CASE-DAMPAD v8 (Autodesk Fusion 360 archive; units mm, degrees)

design "CASE-DAMPAD" references "DAMPAD"
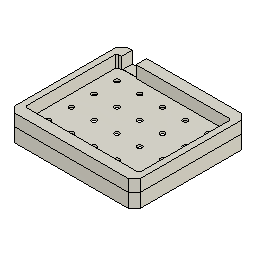
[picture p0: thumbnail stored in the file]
component_insert "コンポーネントの挿入"
ground "固定"
sketch "スケッチ1" plane through (0, 0, 0) normal (0, 0, -1) x axis (1, 0, 0)
  line L1 (2, -78.6) -> (0, -76.6)
  line L2 (95.1, -78.6) -> (2, -78.6)
  line L3 (97.1, -76.6) -> (95.1, -78.6)
  line L4 (97.1, -2) -> (97.1, -76.6)
  line L5 (95.1, 0) -> (97.1, -2)
  line L6 (2, 0) -> (95.1, 0)
  line L7 (0, -2) -> (2, 0)
  line L8 (0, -76.6) -> (0, -2)
  line L9 (-0.2, -76.6828) -> (-0.2, -1.9172)
  line L10 (1.9172, -78.8) -> (-0.2, -76.6828)
  line L11 (95.1828, -78.8) -> (1.9172, -78.8)
  line L12 (97.3, -76.6828) -> (95.1828, -78.8)
  line L13 (97.3, -1.9172) -> (97.3, -76.6828)
  line L14 (95.1828, 0.2) -> (97.3, -1.9172)
  line L15 (1.9172, 0.2) -> (95.1828, 0.2)
  line L16 (-0.2, -1.9172) -> (1.9172, 0.2)
  line L17 (-4, 2.7681) -> (1.2319, 8)
  line L18 (-4, -81.3681) -> (-4, 2.7681)
  line L19 (1.2319, -86.6) -> (-4, -81.3681)
  line L20 (95.8681, -86.6) -> (1.2319, -86.6)
  line L21 (101.1, -81.3681) -> (95.8681, -86.6)
  line L22 (101.1, 2.7681) -> (101.1, -81.3681)
  line L23 (95.8681, 8) -> (101.1, 2.7681)
  line L24 (1.2319, 8) -> (95.8681, 8)
  line L25 (1, -76.1858) -> (1, -2.4142)
  line L26 (2.4142, -77.6) -> (1, -76.1858)
  line L27 (94.6858, -77.6) -> (2.4142, -77.6)
  line L28 (96.1, -76.1858) -> (94.6858, -77.6)
  line L29 (96.1, -2.4142) -> (96.1, -76.1858)
  line L30 (94.6858, -1) -> (96.1, -2.4142)
  line L31 (2.4142, -1) -> (94.6858, -1)
  line L32 (1, -2.4142) -> (2.4142, -1)
  circle C1 centre (67.75, -68) radius 2
  circle C2 centre (10.6, -10.85) radius 2
  circle C3 centre (86.8, -29.9) radius 2
  circle C4 centre (67.75, -48.95) radius 2
  circle C5 centre (67.75, -10.85) radius 2
  circle C6 centre (10.6, -48.95) radius 2
  circle C7 centre (86.8, -48.95) radius 2
  circle C8 centre (48.7, -29.9) radius 2
  circle C9 centre (29.65, -10.85) radius 2
  circle C10 centre (48.7, -68) radius 2
  circle C11 centre (10.6, -68) radius 2
  circle C12 centre (48.7, -10.85) radius 2
  circle C13 centre (29.65, -48.95) radius 2
  circle C14 centre (67.75, -29.9) radius 2
  circle C15 centre (86.8, -10.85) radius 2
  circle C16 centre (10.6, -29.9) radius 2
  circle C17 centre (48.7, -48.95) radius 2
  circle C18 centre (29.65, -29.9) radius 2
  circle C19 centre (29.65, -68) radius 2
  circle C20 centre (86.8, -68) radius 2
  parallel L7 L17
  parallel L8 L18
  parallel L1 L19
  parallel L2 L20
  parallel L3 L21
  parallel L4 L22
  parallel L5 L23
  parallel L6 L24
  dimension "d1" = 0.2
  dimension "d3" = -1
  dimension "d23" distance L4 L22 = 4
  dimension "d24" distance L8 L18 = 4
  dimension "d25" distance L2 L20 = 8
  dimension "d26" distance L6 L24 = 8
  dimension "d27" distance L16 L17 = 6 (= "d30")
  dimension "d28" distance L14 L23 = 6 (= "d30")
  dimension "d29" distance L12 L21 = 6 (= "d30")
  dimension "d30" distance L10 L19 = 6
extrude "押し出し1" new body sketch "スケッチ1" profile of L1 L2 L3 L4 L5 L6 L7 L8 L13 L9 L16 L10 L11 L12 L15 L14 L19 L17 L22 L18 L20 L21 L24 L23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 along normal blind 10 bodies "Bottom"
extrude "押し出し2" add sketch "スケッチ1" profile of L13 L9 L16 L10 L11 L12 L15 L14 L19 L17 L22 L18 L20 L21 L24 L23 against normal blind 1.6
sketch "スケッチ2" plane through (0, 0, 1.6) normal (0, 0, 1) x axis (-1, 0, 0)
  line L1 (0, -76.6) -> (-2, -78.6)
  line L2 (0, -2) -> (0, -76.6)
  line L3 (-2, 0) -> (0, -2)
  line L4 (-95.1, 0) -> (-2, 0)
  line L5 (-97.1, -2) -> (-95.1, 0)
  line L6 (-97.1, -76.6) -> (-97.1, -2)
  line L7 (-95.1, -78.6) -> (-97.1, -76.6)
  line L8 (-2, -78.6) -> (-95.1, -78.6)
  line L9 (-0.8, -2.3314) -> (-0.8, -76.2686)
  line L10 (-2.3314, -0.8) -> (-0.8, -2.3314)
  line L11 (-94.7686, -0.8) -> (-2.3314, -0.8)
  line L12 (-96.3, -2.3314) -> (-94.7686, -0.8)
  line L13 (-96.3, -76.2686) -> (-96.3, -2.3314)
  line L14 (-94.7686, -77.8) -> (-96.3, -76.2686)
  line L15 (-2.3314, -77.8) -> (-94.7686, -77.8)
  line L16 (-0.8, -76.2686) -> (-2.3314, -77.8)
  line L17 (-1.8, -75.3568) -> (-1.8, -74.5354)
  line L18 (-1.8, -89.3214) -> (-1.8, -75.3568)
  line L19 (-10.8, -68.2718) -> (-10.8, -89.3214)
  line L20 (-4.8, -77.8) -> (-4.8, -86.6)
  line L21 (-16.8, -77.8) -> (-16.8, -86.6)
  line L22 (0.2, -1.9172) -> (-1.9172, 0.2)
  line L23 (0.2, -76.6828) -> (0.2, -1.9172)
  line L24 (-1.9172, -78.8) -> (0.2, -76.6828)
  line L25 (-95.1828, -78.8) -> (-1.9172, -78.8)
  line L26 (-97.3, -76.6828) -> (-95.1828, -78.8)
  line L27 (-97.3, -1.9172) -> (-97.3, -76.6828)
  line L28 (-95.1828, 0.2) -> (-97.3, -1.9172)
  line L29 (-1.9172, 0.2) -> (-95.1828, 0.2)
  line L30 (-95.8681, 8) -> (-1.2319, 8)
  line L31 (-101.1, 2.7681) -> (-95.8681, 8)
  line L32 (-101.1, -81.3681) -> (-101.1, 2.7681)
  line L33 (-95.8681, -86.6) -> (-101.1, -81.3681)
  line L34 (-1.2319, -86.6) -> (-95.8681, -86.6)
  line L35 (4, -81.3681) -> (-1.2319, -86.6)
  line L36 (4, 2.7681) -> (4, -81.3681)
  line L37 (-1.2319, 8) -> (4, 2.7681)
  circle C1 centre (-67.75, -68) radius 2
  circle C2 centre (-10.6, -10.85) radius 2
  circle C3 centre (-86.8, -29.9) radius 2
  circle C4 centre (-67.75, -48.95) radius 2
  circle C5 centre (-67.75, -10.85) radius 2
  circle C6 centre (-10.6, -48.95) radius 2
  circle C7 centre (-86.8, -48.95) radius 2
  circle C8 centre (-48.7, -29.9) radius 2
  circle C9 centre (-29.65, -10.85) radius 2
  circle C10 centre (-48.7, -68) radius 2
  circle C11 centre (-10.6, -68) radius 2
  circle C12 centre (-48.7, -10.85) radius 2
  circle C13 centre (-29.65, -48.95) radius 2
  circle C14 centre (-67.75, -29.9) radius 2
  circle C15 centre (-86.8, -10.85) radius 2
  circle C16 centre (-10.6, -29.9) radius 2
  circle C17 centre (-48.7, -48.95) radius 2
  circle C18 centre (-29.65, -29.9) radius 2
  circle C19 centre (-29.65, -68) radius 2
  circle C20 centre (-86.8, -68) radius 2
  point P23 (-4.8, -77.8)
  point P24 (-16.8, -77.8)
  point P41 (-16.8, -86.6)
  point P42 (-4.8, -86.6)
  vertical L17
  parallel L17 L18
  perpendicular L15 L19
  coincident L15 P23
  perpendicular L15 L20
  coincident L15 P24
  perpendicular L15 L21
  symmetric L19 L20 L21
  coincident L34 P41
  coincident L34 P42
  dimension "d9" = -0.8
  dimension "d13" distance L9 L18 = 1
  dimension "d14" distance L18 L19 = 9
  dimension "d15" distance L20 L21 = 12
extrude "押し出し5" new body sketch "スケッチ2" profile of L1 L2 L3 L4 L5 L6 L7 L8 L9 L10 L12 L11 L16 L13 L14 L15 L20 L21 L22 L23 L24 L25 L26 L27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 along normal blind 10 bodies "Top"
sketch "スケッチ3" plane through (0, 0, 11.6) normal (0, 0, 1) x axis (-1, 0, 0)
  line L1 (-93.1, 4) -> (-4, 4)
  line L2 (-3, 4) -> (-3.5, 3.134)
  line L3 (-3.5, 4.866) -> (-3, 4)
  line L4 (-4.5, 4.866) -> (-3.5, 4.866)
  line L5 (-5, 4) -> (-4.5, 4.866)
  line L6 (-4.5, 3.134) -> (-5, 4)
  line L7 (-3.5, 3.134) -> (-4.5, 3.134)
  line L8 (-2.4142, -77.6) -> (-1, -76.1858)
  line L9 (-94.6858, -77.6) -> (-17, -77.6)
  line L10 (-96.1, -76.1858) -> (-94.6858, -77.6)
  line L11 (-96.1, -2.4142) -> (-96.1, -76.1858)
  line L12 (-94.6858, -1) -> (-96.1, -2.4142)
  line L13 (-2.4142, -1) -> (-94.6858, -1)
  line L14 (-1, -2.4142) -> (-2.4142, -1)
  line L15 (-1, -76.1858) -> (-1, -2.4142)
  line L16 (-95.8681, 8) -> (-1.2319, 8)
  line L17 (-101.1, -81.3681) -> (-101.1, 2.7681)
  line L18 (-93.6, 4.866) -> (-92.6, 4.866)
  line L19 (-94.1, 4) -> (-93.6, 4.866)
  line L20 (-92.6, 4.866) -> (-92.1, 4)
  line L21 (-92.1, 4) -> (-92.6, 3.134)
  line L22 (-93.6, 3.134) -> (-94.1, 4)
  line L23 (-92.6, 3.134) -> (-93.6, 3.134)
  line L24 (-17, -77.6) -> (-17, -86.6)
  line L25 (-5, -77.6) -> (-2.4142, -77.6)
  line L26 (-5, -86.6) -> (-5, -77.6)
  line L27 (-3.5, -82.6) -> (-3, -81.734)
  line L28 (-2, -81.734) -> (-1.5, -82.6)
  line L29 (-1.5, -82.6) -> (-2, -83.466)
  line L30 (-3, -81.734) -> (-2, -81.734)
  line L31 (-2, -83.466) -> (-3, -83.466)
  line L32 (-3, -83.466) -> (-3.5, -82.6)
  line L33 (-17, -86.6) -> (-95.8681, -86.6)
  line L34 (-93.1, -82.6) -> (-2.5, -82.6)
  line L35 (-20.5, -82.6) -> (-20, -81.734)
  line L36 (-19, -83.466) -> (-20, -83.466)
  line L37 (-19, -81.734) -> (-18.5, -82.6)
  line L38 (-20, -83.466) -> (-20.5, -82.6)
  line L39 (-20, -81.734) -> (-19, -81.734)
  line L40 (-18.5, -82.6) -> (-19, -83.466)
  line L41 (-94.1, -82.6) -> (-93.6, -81.734)
  line L42 (-92.6, -83.466) -> (-93.6, -83.466)
  line L43 (-92.6, -81.734) -> (-92.1, -82.6)
  line L44 (-93.6, -83.466) -> (-94.1, -82.6)
  line L45 (-93.6, -81.734) -> (-92.6, -81.734)
  line L46 (-92.1, -82.6) -> (-92.6, -83.466)
  line L47 (-17, -77.6) -> (-17, -86.6)
  line L48 (-5, -86.6) -> (-5, -77.6)
  line L49 (4, 2.7681) -> (4, -81.3681)
  line L50 (-1.2319, -86.6) -> (-5, -86.6)
  line L51 (4, -81.3681) -> (-1.2319, -86.6)
  line L52 (4, 2.7681) -> (4, -81.3681)
  line L53 (-1.2319, 8) -> (4, 2.7681)
  line L54 (-95.8681, 8) -> (-1.2319, 8)
  line L55 (-101.1, 2.7681) -> (-95.8681, 8)
  line L56 (-101.1, -81.3681) -> (-101.1, 2.7681)
  line L57 (-95.8681, -86.6) -> (-101.1, -81.3681)
  line L58 (-17, -86.6) -> (-95.8681, -86.6)
  line L59 (-1.2319, -86.6) -> (-4.8, -86.6)
  line L60 (4, -81.3681) -> (-1.2319, -86.6)
  line L61 (4, 2.7681) -> (4, -81.3681)
  line L62 (-1.2319, 8) -> (4, 2.7681)
  line L63 (-95.8681, 8) -> (-1.2319, 8)
  line L64 (-101.1, 2.7681) -> (-95.8681, 8)
  line L65 (-101.1, -81.3681) -> (-101.1, 2.7681)
  line L66 (-95.8681, -86.6) -> (-101.1, -81.3681)
  line L67 (-16.8, -86.6) -> (-95.8681, -86.6)
  line L68 (-16.8, -77.8) -> (-16.8, -86.6)
  line L69 (-94.7686, -77.8) -> (-16.8, -77.8)
  line L70 (-96.3, -76.2686) -> (-94.7686, -77.8)
  line L71 (-96.3, -2.3314) -> (-96.3, -76.2686)
  line L72 (-94.7686, -0.8) -> (-96.3, -2.3314)
  line L73 (-2.3314, -0.8) -> (-94.7686, -0.8)
  line L74 (-0.8, -2.3314) -> (-2.3314, -0.8)
  line L75 (-0.8, -76.2686) -> (-0.8, -2.3314)
  line L76 (-2.3314, -77.8) -> (-0.8, -76.2686)
  line L77 (-4.8, -77.8) -> (-2.3314, -77.8)
  line L78 (-4.8, -86.6) -> (-4.8, -77.8)
  circle C1 centre (-4, 4) radius 1.2
  circle C2 centre (-4, 4) radius 1.95
  circle C3 centre (-4, 4) radius 1
  circle C4 centre (-93.1, 4) radius 1.95
  circle C5 centre (-93.1, 4) radius 1
  circle C6 centre (-93.1, 4) radius 1.2
  circle C7 centre (-2.5, -82.6) radius 1.95
  circle C8 centre (-2.5, -82.6) radius 1.2
  circle C9 centre (-2.5, -82.6) radius 1
  circle C10 centre (-19.5, -82.6) radius 1.2
  circle C11 centre (-19.5, -82.6) radius 1.95
  circle C12 centre (-19.5, -82.6) radius 1
  circle C13 centre (-93.1, -82.6) radius 1.2
  circle C14 centre (-93.1, -82.6) radius 1.95
  circle C15 centre (-93.1, -82.6) radius 1
  point P2 (-4, 4)
  point P3 (-4, 4)
  point P5 (-4, 4)
  point P13 (-4, 4)
  point P12 (-4.5, 3.134)
  point P30 (-93.1, 4)
  point P31 (-93.1, 4)
  point P29 (-93.1, 4)
  point P36 (-93.1, 4)
  point P35 (-93.6, 3.134)
  point P4 (-93.1, 4)
  point P27 (-93.1, 4)
  point P44 (-2.5, -82.6)
  point P45 (-2.5, -82.6)
  point P43 (-2.5, -82.6)
  point P50 (-2.5, -82.6)
  point P49 (-3, -83.466)
  point P41 (-2.5, -82.6)
  point P54 (-2.5, -82.6)
  point P63 (-19.5, -82.6)
  point P64 (-19.5, -82.6)
  point P57 (-19.5, -82.6)
  point P65 (-19.5, -82.6)
  point P60 (-20, -83.466)
  point P58 (-19.5, -82.6)
  point P67 (-19.5, -82.6)
  point P75 (-93.1, -82.6)
  point P76 (-93.1, -82.6)
  point P69 (-93.1, -82.6)
  point P77 (-93.1, -82.6)
  point P72 (-93.6, -83.466)
  point P70 (-93.1, -82.6)
  point P79 (-93.1, -82.6)
  point P55 (-93.1, -82.6)
  point P6 (-4, 4)
  coincident P2 P3
  coincident P3 P5
  concentric C1 C3
  coincident P2 P13
  coincident C3 P12
  horizontal L7
  coincident P30 P31
  coincident P29 P31
  concentric C5 C6
  coincident P30 P36
  coincident P35 C5
  horizontal L23
  coincident P4 P27
  coincident P44 P45
  coincident P43 P45
  concentric C8 C9
  coincident P44 P50
  coincident P49 C9
  horizontal L31
  coincident P41 P54
  parallel L33 L34
  coincident P63 P64
  coincident P57 P64
  concentric C10 C12
  coincident P63 P65
  coincident P60 C12
  horizontal L36
  coincident P58 P67
  coincident P75 P76
  coincident P69 P76
  concentric C13 C15
  coincident P75 P77
  coincident P72 C15
  horizontal L42
  coincident P70 P79
  coincident P55 P76
  coincident L34 P67
  dimension "d20" diameter C1 = 2.4
  dimension "d21" diameter C2 = 3.9
  dimension "d22" diameter C3 = 2
  dimension "d31" distance L1 L16 = 4
  dimension "d33" distance P4 L17 = 8
  dimension "d34" diameter C6 = 2.4
  dimension "d35" diameter C4 = 3.9
  dimension "d36" diameter C5 = 2
  dimension "d37" diameter C8 = 2.4
  dimension "d38" diameter C7 = 3.9
  dimension "d39" diameter C9 = 2
  dimension "d40" distance P41 L33 = 4
  dimension "d42" diameter C10 = 2.4
  dimension "d43" diameter C11 = 3.9
  dimension "d44" diameter C12 = 2
  dimension "d45" diameter C13 = 2.4
  dimension "d46" diameter C14 = 3.9
  dimension "d47" diameter C15 = 2
  dimension "d48" distance P63 L47 = 2.5
  dimension "d49" distance P41 L48 = 2.5
  dimension "d50" distance L17 P77 = 8
  dimension "d51" distance P6 L49 = 8
extrude "押し出し3" sketch "スケッチ3" profile of C1 C2 L2 L3 L4 L5 L6 L7 L18 C4 L19 C6 L20 L21 L22 L23 L27 C7 L28 C8 L29 L30 L31 L32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 no distance stored from offset -2
extrude "押し出し4" cut sketch "スケッチ3" profile of C1 L2 L3 L4 L5 L6 L7 L18 L19 C6 L20 L21 L22 L23 L27 L28 C8 L29 L30 L31 L32 L35 C10 L36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 to an object offset -0.2
extrude "押し出し6" sketch "スケッチ3" profile of L2 L3 L4 L5 L6 L7 L18 L19 L20 L21 L22 L23 L27 L28 L29 L30 L31 L32 L35 L36 L37 L38 L39 L40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 blind 8 taper -1
named bodies: "Bottom", "Top"

design "DAMPAD"
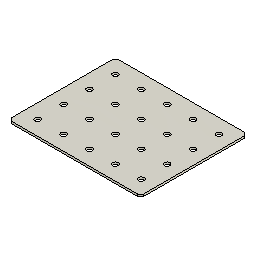
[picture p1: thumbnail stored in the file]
sketch "スケッチ1" plane through (0, 0, 0) normal (0, 0, 1) x axis (1, 0, 0)
  line L1 (97.1, 0) -> (0, 0)
  line L2 (97.1, 78.6) -> (97.1, 0)
  line L3 (0, 78.6) -> (97.1, 78.6)
  line L4 (0, 0) -> (0, 78.6)
  point P1 (0, 0)
  point P2 (0, 0)
  point P5 (0, 78.6)
  horizontal L1
  vertical L2
  horizontal L3
  vertical L4
  coincident P1 P2
  dimension "d1" distance P2 P5 = 78.6
  dimension "d2" distance L2 L4 = 97.1
extrude "押し出し1" new body sketch "スケッチ1" along normal blind 1.6
chamfer "面取り" distance 2
sketch "スケッチ2" plane through (0, 0, 1.6) normal (0, 0, 1) x axis (-1, 0, 0)
  line L1 (0, -76.6) -> (-2, -78.6)
  line L2 (0, -2) -> (0, -76.6)
  line L3 (-2, 0) -> (0, -2)
  line L4 (-95.1, 0) -> (-2, 0)
  line L5 (-97.1, -2) -> (-95.1, 0)
  line L6 (-97.1, -76.6) -> (-97.1, -2)
  line L7 (-95.1, -78.6) -> (-97.1, -76.6)
  line L8 (-2, -78.6) -> (-95.1, -78.6)
  circle C1 centre (-86.8, -68) radius 2
  circle C2 centre (-67.75, -68) radius 2
  circle C3 centre (-48.7, -68) radius 2
  circle C4 centre (-29.65, -68) radius 2
  circle C5 centre (-10.6, -68) radius 2
  circle C6 centre (-86.8, -48.95) radius 2
  circle C7 centre (-67.75, -48.95) radius 2
  circle C8 centre (-48.7, -48.95) radius 2
  circle C9 centre (-29.65, -48.95) radius 2
  circle C10 centre (-10.6, -48.95) radius 2
  circle C11 centre (-86.8, -29.9) radius 2
  circle C12 centre (-67.75, -29.9) radius 2
  circle C13 centre (-48.7, -29.9) radius 2
  circle C14 centre (-29.65, -29.9) radius 2
  circle C15 centre (-10.6, -29.9) radius 2
  circle C16 centre (-86.8, -10.85) radius 2
  circle C17 centre (-67.75, -10.85) radius 2
  circle C18 centre (-48.7, -10.85) radius 2
  circle C19 centre (-29.65, -10.85) radius 2
  circle C20 centre (-10.6, -10.85) radius 2
  point P10 (-86.8, -68)
  point P15 (-86.8, -48.95)
  dimension "d6" diameter C1 = 4
  dimension "d7" distance L8 P10 = 10.6
  dimension "d8" distance L6 P10 = 10.3
  dimension "d13" distance P10 P15 = 19.05
  dimension "d14" = 11.35
  dimension "d15" = 9.9
  dimension "d11" R-Pattern1-uDistance = 19.05
  dimension "d12" R-Pattern1-vDistance = 19.05
extrude "押し出し2" cut sketch "スケッチ2" profile of C1 C2 C3 C4 C5 C6 C7 C8 C9 C10 C11 C12 C13 C14 C15 C16 C17 C18 C19 C20 no distance stored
